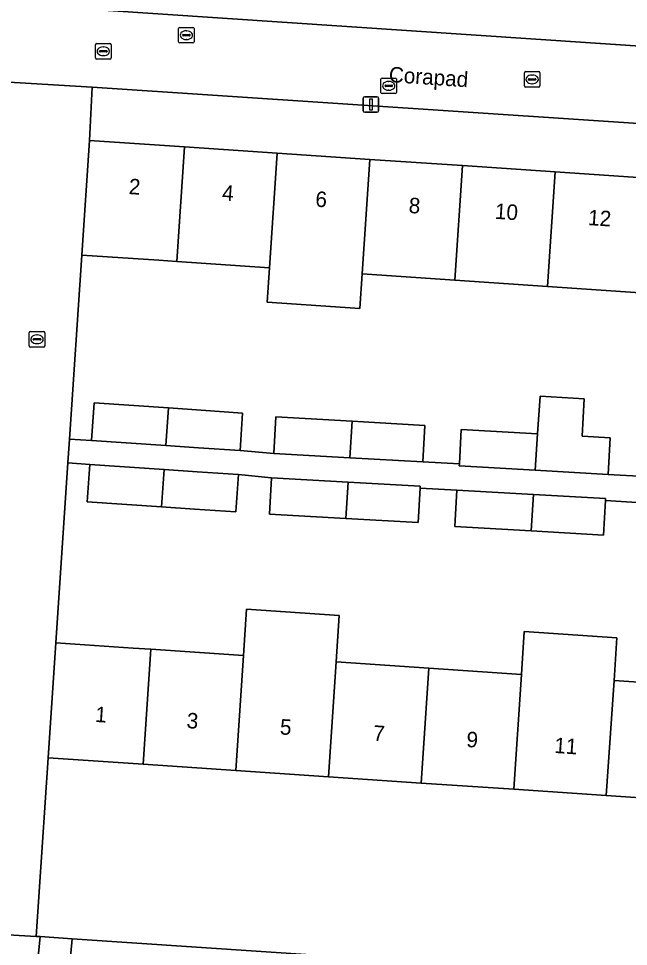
# Model space of a CAD drawing. Extents: x 161848 to 162726, y 385382 to 386521.
# Drawn here: x 162057.8 to 162097.2, y 385869.2 to 385929.1 of the extents above; entities that cross this region are included whole.
import ezdxf

# ---------------------------------------------------------------- set-up
doc = ezdxf.new("R2010")
doc.units = 0
for name, color, linetype in [('IMGEO_Brandkraan', 7, 'Continuous'), ('IMGEO_Erf', 7, 'Continuous'), ('IMGEO_Kolk', 7, 'Continuous'), ('IMGEO_Lichtmast', 7, 'Continuous'), ('IMGEO_Muur', 7, 'Continuous'), ('IMGEO_Openbare_ruimte_label', 7, 'Continuous'), ('IMGEO_Pand', 7, 'Continuous'), ('IMGEO_Pand_nummerreeks', 7, 'Continuous'), ('IMGEO_Rijbaan_lokaal_open', 7, 'Continuous'), ('IMGEO_Rioolput', 7, 'Continuous'), ('IMGEO_Voetpad_open', 7, 'Continuous'), ('IMGEO_Woonerf_open', 7, 'Continuous')]:
    doc.layers.add(name, color=color, linetype=linetype)

msp = doc.modelspace()

# ---------------------------------------------------------------- linework, layer by layer
at = {"layer": 'IMGEO_Brandkraan'}
for p, q in [((162081.246, 385924.369), (162081.246, 385925.221)), ((162081.321, 385925.295), (162082.173, 385925.295)), ((162081.734, 385925.075), (162081.759, 385925.075)), ((162082.247, 385925.221), (162082.247, 385924.369)), ((162082.173, 385924.295), (162081.321, 385924.295)), ((162081.505, 385924.789), (162081.505, 385924.801)), ((162081.943, 385924.752), (162081.545, 385924.752)), ((162081.548, 385924.838), (162081.946, 385924.838)), ((162081.757, 385924.515), (162081.732, 385924.515)), ((162081.989, 385924.801), (162081.989, 385924.789))]:
    msp.add_line(p, q, dxfattribs=at)
for points in [[(162081.246, 385924.369), (162081.246, 385925.221)], [(162081.321, 385925.295), (162082.173, 385925.295)], [(162082.247, 385925.221), (162082.247, 385924.369)], [(162082.173, 385924.295), (162081.321, 385924.295)]]:
    msp.add_lwpolyline(points, dxfattribs=at)
for centre, radius, start, end in [((162081.323, 385925.219), 0.0765, 91.55205, 178.44795), ((162081.323, 385925.219), 0.0765, 91.55205, 178.44795), ((162082.171, 385925.219), 0.0765, 1.55205, 88.44795), ((162082.171, 385925.219), 0.0765, 1.55205, 88.44795), ((162081.323, 385924.371), 0.0765, 181.55205, 268.44795), ((162081.323, 385924.371), 0.0765, 181.55205, 268.44795), ((162081.545, 385924.798), 0.0403, 85.87752, 175.75265), ((162081.542, 385924.788), 0.0366, 178.93798, 274.71019), ((162081.946, 385924.795), 0.043, 264.86636, 352.45326), ((162081.95, 385924.8), 0.0386, 1.73085, 96.63898), ((162082.171, 385924.371), 0.0765, 271.55205, 358.44795), ((162082.171, 385924.371), 0.0765, 271.55205, 358.44795)]:
    msp.add_arc(centre, radius, start, end, dxfattribs=at)
for centre, major_axis, ratio, start_param, end_param in [((162081.733, 385924.795), (-0.387, 0.002), 0.722429, 4.712389, 7.853982), ((162081.758, 385924.795), (-0.39, 0.002), 0.717154, 1.570796, 4.712389)]:
    msp.add_ellipse(centre, major_axis=major_axis, ratio=ratio, start_param=start_param, end_param=end_param, dxfattribs=at)
at = {"layer": 'IMGEO_Erf'}
for points in [[(162111.951, 385937.967), (162105.776, 385938.384), (162099.785, 385938.788), (162093.802, 385939.192), (162087.814, 385939.596), (162081.834, 385939.999), (162075.835, 385940.404), (162069.859, 385940.808), (162063.747, 385941.22), (162062.973, 385929.704), (162111.178, 385926.464)], [(162110.864, 385921.497), (162062.576, 385924.706), (162062.409, 385921.268), (162068.56, 385920.853), (162074.547, 385920.449), (162080.533, 385920.045), (162086.52, 385919.641), (162092.506, 385919.236), (162098.492, 385918.832), (162104.479, 385918.428), (162110.632, 385918.013)], [(162107.935, 385878.155), (162101.794, 385878.569), (162095.807, 385878.973), (162089.821, 385879.377), (162083.835, 385879.781), (162077.848, 385880.186), (162071.862, 385880.59), (162065.875, 385880.994), (162059.734, 385881.408), (162058.972, 385869.883), (162059.222, 385869.866), (162061.295, 385869.726), (162085.397, 385868.102), (162087.531, 385867.959), (162107.159, 385866.636)]]:
    msp.add_lwpolyline(points, close=True, dxfattribs=at)
for points in [[(162097.992, 385911.436), (162092.006, 385911.84), (162086.02, 385912.244), (162080.033, 385912.648), (162079.884, 385910.429), (162073.897, 385910.834), (162074.047, 385913.052), (162068.06, 385913.456), (162066.899, 385913.534), (162061.91, 385913.871), (162061.115, 385901.991), (162062.543, 385901.895), (162062.706, 385904.319), (162067.507, 385903.995), (162069.631, 385903.852), (162072.304, 385903.662), (162072.138, 385901.245), (162074.33, 385901.063), (162074.463, 385903.417), (162079.39, 385903.138), (162084.08, 385902.873), (162083.947, 385900.519), (162086.31, 385900.385), (162086.436, 385902.608), (162091.363, 385902.329), (162091.527, 385904.756), (162094.38, 385904.595), (162094.243, 385902.166), (162096.053, 385902.064), (162095.92, 385899.71), (162098.283, 385899.576)], [(162098.118, 385897.88), (162095.755, 385898.014), (162095.629, 385895.79), (162090.947, 385896.055), (162086.012, 385896.334), (162086.145, 385898.688), (162083.782, 385898.822), (162083.656, 385896.599), (162078.974, 385896.864), (162074.039, 385897.143), (162074.172, 385899.497), (162072.034, 385899.699), (162071.871, 385897.286), (162069.196, 385897.467), (162067.075, 385897.61), (162062.271, 385897.934), (162062.434, 385900.348), (162061.012, 385900.444), (162060.235, 385888.83), (162065.224, 385888.493), (162066.376, 385888.417), (162072.363, 385888.013), (162072.565, 385891.006), (162078.551, 385890.602), (162078.349, 385887.609), (162084.336, 385887.204), (162090.322, 385886.799), (162090.507, 385889.565), (162096.492, 385889.161), (162096.308, 385886.395), (162102.295, 385885.991)]]:
    msp.add_lwpolyline(points, dxfattribs=at)
at = {"layer": 'IMGEO_Kolk'}
for p, q in [((162062.803, 385926.6), (162062.803, 385927.452)), ((162062.878, 385927.526), (162063.73, 385927.526)), ((162063.291, 385927.306), (162063.316, 385927.306)), ((162063.804, 385927.452), (162063.804, 385926.6)), ((162063.062, 385927.02), (162063.062, 385927.032)), ((162063.5, 385926.983), (162063.102, 385926.983)), ((162063.105, 385927.069), (162063.503, 385927.069)), ((162063.314, 385926.746), (162063.289, 385926.746)), ((162063.546, 385927.032), (162063.546, 385927.02)), ((162063.73, 385926.526), (162062.878, 385926.526)), ((162090.514, 385924.785), (162090.514, 385925.637)), ((162090.589, 385925.711), (162091.441, 385925.711)), ((162091.002, 385925.491), (162091.027, 385925.491)), ((162091.515, 385925.637), (162091.515, 385924.785)), ((162090.773, 385925.205), (162090.773, 385925.217)), ((162091.211, 385925.168), (162090.813, 385925.168)), ((162090.816, 385925.254), (162091.214, 385925.254)), ((162091.025, 385924.931), (162091, 385924.931)), ((162091.257, 385925.217), (162091.257, 385925.205)), ((162091.441, 385924.711), (162090.589, 385924.711)), ((162058.519, 385908.006), (162058.519, 385908.858)), ((162058.594, 385908.932), (162059.446, 385908.932)), ((162059.007, 385908.712), (162059.032, 385908.712)), ((162059.52, 385908.858), (162059.52, 385908.006)), ((162058.778, 385908.426), (162058.778, 385908.438)), ((162059.216, 385908.389), (162058.818, 385908.389)), ((162058.821, 385908.475), (162059.219, 385908.475)), ((162059.03, 385908.152), (162059.005, 385908.152)), ((162059.262, 385908.438), (162059.262, 385908.426)), ((162059.446, 385907.932), (162058.594, 385907.932))]:
    msp.add_line(p, q, dxfattribs=at)
for points in [[(162062.803, 385926.6), (162062.803, 385927.452)], [(162062.878, 385927.526), (162063.73, 385927.526)], [(162063.804, 385927.452), (162063.804, 385926.6)], [(162063.73, 385926.526), (162062.878, 385926.526)], [(162090.514, 385924.785), (162090.514, 385925.637)], [(162090.589, 385925.711), (162091.441, 385925.711)], [(162091.515, 385925.637), (162091.515, 385924.785)], [(162091.441, 385924.711), (162090.589, 385924.711)], [(162058.519, 385908.006), (162058.519, 385908.858)], [(162058.594, 385908.932), (162059.446, 385908.932)], [(162059.52, 385908.858), (162059.52, 385908.006)], [(162059.446, 385907.932), (162058.594, 385907.932)]]:
    msp.add_lwpolyline(points, dxfattribs=at)
for centre, radius, start, end in [((162062.88, 385927.45), 0.0765, 91.55205, 178.44795), ((162062.88, 385927.45), 0.0765, 91.55205, 178.44795), ((162063.728, 385927.45), 0.0765, 1.55205, 88.44795), ((162063.728, 385927.45), 0.0765, 1.55205, 88.44795), ((162063.102, 385927.029), 0.0403, 85.87752, 175.75265), ((162063.099, 385927.019), 0.0366, 178.93798, 274.71019), ((162063.503, 385927.026), 0.043, 264.86636, 352.45326), ((162063.507, 385927.031), 0.0386, 1.73085, 96.63898), ((162062.88, 385926.602), 0.0765, 181.55205, 268.44795), ((162062.88, 385926.602), 0.0765, 181.55205, 268.44795), ((162063.728, 385926.602), 0.0765, 271.55205, 358.44795), ((162063.728, 385926.602), 0.0765, 271.55205, 358.44795), ((162090.591, 385925.635), 0.0765, 91.55205, 178.44795), ((162090.591, 385925.635), 0.0765, 91.55205, 178.44795), ((162091.439, 385925.635), 0.0765, 1.55205, 88.44795), ((162091.439, 385925.635), 0.0765, 1.55205, 88.44795), ((162090.813, 385925.214), 0.0403, 85.87752, 175.75265), ((162090.81, 385925.204), 0.0366, 178.93798, 274.71019), ((162091.214, 385925.211), 0.043, 264.86636, 352.45326), ((162091.218, 385925.216), 0.0386, 1.73085, 96.63898), ((162090.591, 385924.787), 0.0765, 181.55205, 268.44795), ((162090.591, 385924.787), 0.0765, 181.55205, 268.44795), ((162091.439, 385924.787), 0.0765, 271.55205, 358.44795), ((162091.439, 385924.787), 0.0765, 271.55205, 358.44795), ((162058.596, 385908.856), 0.0765, 91.55205, 178.44795), ((162058.596, 385908.856), 0.0765, 91.55205, 178.44795), ((162059.444, 385908.856), 0.0765, 1.55205, 88.44795), ((162059.444, 385908.856), 0.0765, 1.55205, 88.44795), ((162058.818, 385908.435), 0.0403, 85.87752, 175.75265), ((162058.815, 385908.425), 0.0366, 178.93798, 274.71019), ((162059.219, 385908.432), 0.043, 264.86636, 352.45326), ((162059.223, 385908.437), 0.0386, 1.73085, 96.63898), ((162058.596, 385908.008), 0.0765, 181.55205, 268.44795), ((162058.596, 385908.008), 0.0765, 181.55205, 268.44795), ((162059.444, 385908.008), 0.0765, 271.55205, 358.44795), ((162059.444, 385908.008), 0.0765, 271.55205, 358.44795)]:
    msp.add_arc(centre, radius, start, end, dxfattribs=at)
for centre, major_axis, ratio, start_param, end_param in [((162063.29, 385927.026), (-0.387, 0.002), 0.722429, 4.712389, 7.853982), ((162063.315, 385927.026), (-0.39, 0.002), 0.717154, 1.570796, 4.712389), ((162091.001, 385925.211), (-0.387, 0.002), 0.722429, 4.712389, 7.853982), ((162091.026, 385925.211), (-0.39, 0.002), 0.717154, 1.570796, 4.712389), ((162059.006, 385908.432), (-0.387, 0.002), 0.722429, 4.712389, 7.853982), ((162059.031, 385908.432), (-0.39, 0.002), 0.717154, 1.570796, 4.712389)]:
    msp.add_ellipse(centre, major_axis=major_axis, ratio=ratio, start_param=start_param, end_param=end_param, dxfattribs=at)
at = {"layer": 'IMGEO_Lichtmast'}
for p, q in [((162080.098, 385923.189), (162080.098, 385923.989)), ((162080.098, 385923.989), (162080.098, 385923.189)), ((162080.198, 385924.089), (162080.988, 385924.089)), ((162080.988, 385924.089), (162080.198, 385924.089)), ((162081.088, 385923.989), (162081.088, 385923.189)), ((162081.088, 385923.189), (162081.088, 385923.989)), ((162080.988, 385923.089), (162080.198, 385923.089)), ((162080.198, 385923.089), (162080.988, 385923.089))]:
    msp.add_line(p, q, dxfattribs=at)
msp.add_lwpolyline([(162080.518, 385923.964), (162080.668, 385923.964), (162080.668, 385923.214), (162080.518, 385923.214), (162080.518, 385923.964)], dxfattribs=at)
for centre, start, end in [((162080.198, 385923.989), 90, 180), ((162080.198, 385923.989), 90, 180), ((162080.988, 385923.989), 0, 90), ((162080.988, 385923.989), 360, 90), ((162080.198, 385923.189), 180, 270), ((162080.198, 385923.189), 180, 270), ((162080.988, 385923.189), 270, 0), ((162080.988, 385923.189), 270, 0)]:
    msp.add_arc(centre, 0.1, start, end, dxfattribs=at)
at = {"layer": 'IMGEO_Muur'}
for points in [[(162061.115, 385901.991), (162061.91, 385913.871)], [(162061.012, 385900.444), (162060.235, 385888.83)]]:
    msp.add_lwpolyline(points, dxfattribs=at)
at = {"layer": 'IMGEO_Pand'}
for points in [[(162061.91, 385913.871), (162066.899, 385913.534), (162068.06, 385913.456), (162068.56, 385920.853), (162062.409, 385921.268)], [(162074.547, 385920.449), (162068.56, 385920.853), (162068.06, 385913.456), (162074.047, 385913.052)], [(162073.897, 385910.834), (162079.884, 385910.429), (162080.033, 385912.648), (162080.533, 385920.045), (162074.547, 385920.449), (162074.047, 385913.052)], [(162080.033, 385912.648), (162086.02, 385912.244), (162086.52, 385919.641), (162080.533, 385920.045)], [(162092.506, 385919.236), (162086.52, 385919.641), (162086.02, 385912.244), (162092.006, 385911.84)], [(162098.492, 385918.832), (162092.506, 385919.236), (162092.006, 385911.84), (162097.992, 385911.436)], [(162096.053, 385902.064), (162094.243, 385902.166), (162094.38, 385904.595), (162091.527, 385904.756), (162091.363, 385902.329), (162091.204, 385899.976), (162095.92, 385899.71)], [(162062.706, 385904.319), (162062.543, 385901.895), (162067.343, 385901.571), (162067.507, 385903.995)], [(162069.465, 385901.428), (162072.138, 385901.245), (162072.304, 385903.662), (162069.631, 385903.852), (162067.507, 385903.995), (162067.343, 385901.571)], [(162074.463, 385903.417), (162074.33, 385901.063), (162079.231, 385900.785), (162079.39, 385903.138)], [(162083.947, 385900.519), (162084.08, 385902.873), (162079.39, 385903.138), (162079.231, 385900.785)], [(162091.363, 385902.329), (162086.436, 385902.608), (162086.31, 385900.385), (162086.303, 385900.254), (162091.204, 385899.976)], [(162062.434, 385900.348), (162062.271, 385897.934), (162067.075, 385897.61), (162067.238, 385900.023)], [(162069.196, 385897.467), (162071.871, 385897.286), (162072.034, 385899.699), (162069.36, 385899.88), (162067.238, 385900.023), (162067.075, 385897.61)], [(162074.172, 385899.497), (162074.039, 385897.143), (162078.974, 385896.864), (162079.132, 385899.216)], [(162083.782, 385898.822), (162083.789, 385898.953), (162079.132, 385899.216), (162078.974, 385896.864), (162083.656, 385896.599)], [(162086.145, 385898.688), (162086.012, 385896.334), (162090.947, 385896.055), (162091.106, 385898.407)], [(162095.755, 385898.014), (162095.762, 385898.144), (162091.106, 385898.407), (162090.947, 385896.055), (162095.629, 385895.79)], [(162078.551, 385890.602), (162072.565, 385891.006), (162072.363, 385888.013), (162071.862, 385880.59), (162077.848, 385880.186), (162078.349, 385887.609)], [(162089.821, 385879.377), (162095.807, 385878.973), (162096.308, 385886.395), (162096.492, 385889.161), (162090.507, 385889.565), (162090.322, 385886.799)], [(162059.734, 385881.408), (162065.875, 385880.994), (162066.376, 385888.417), (162065.224, 385888.493), (162060.235, 385888.83)], [(162065.875, 385880.994), (162071.862, 385880.59), (162072.363, 385888.013), (162066.376, 385888.417)], [(162077.848, 385880.186), (162083.835, 385879.781), (162084.336, 385887.204), (162078.349, 385887.609)], [(162090.322, 385886.799), (162084.336, 385887.204), (162083.835, 385879.781), (162089.821, 385879.377)], [(162102.295, 385885.991), (162096.308, 385886.395), (162095.807, 385878.973), (162101.794, 385878.569)]]:
    msp.add_lwpolyline(points, close=True, dxfattribs=at)
at = {"layer": 'IMGEO_Rijbaan_lokaal_open'}
msp.add_lwpolyline([(162050.963, 385870.339), (162058.972, 385869.883), (162059.734, 385881.408), (162060.235, 385888.83), (162061.012, 385900.444), (162061.115, 385901.991), (162061.91, 385913.871), (162062.409, 385921.268), (162062.576, 385924.706), (162054.686, 385925.183)], dxfattribs=at)
at = {"layer": 'IMGEO_Rioolput'}
for p, q in [((162068.171, 385927.639), (162068.171, 385928.491)), ((162068.246, 385928.565), (162069.098, 385928.565)), ((162069.172, 385928.491), (162069.172, 385927.639)), ((162068.43, 385928.059), (162068.43, 385928.071)), ((162068.868, 385928.022), (162068.47, 385928.022)), ((162068.473, 385928.108), (162068.871, 385928.108)), ((162068.659, 385928.345), (162068.684, 385928.345)), ((162068.914, 385928.071), (162068.914, 385928.059)), ((162069.098, 385927.565), (162068.246, 385927.565)), ((162068.682, 385927.785), (162068.657, 385927.785))]:
    msp.add_line(p, q, dxfattribs=at)
for points in [[(162068.171, 385927.639), (162068.171, 385928.491)], [(162068.246, 385928.565), (162069.098, 385928.565)], [(162069.172, 385928.491), (162069.172, 385927.639)], [(162069.098, 385927.565), (162068.246, 385927.565)]]:
    msp.add_lwpolyline(points, dxfattribs=at)
for centre, radius, start, end in [((162068.248, 385928.489), 0.0765, 91.55205, 178.44795), ((162068.248, 385928.489), 0.0765, 91.55205, 178.44795), ((162069.096, 385928.489), 0.0765, 1.55205, 88.44795), ((162069.096, 385928.489), 0.0765, 1.55205, 88.44795), ((162068.47, 385928.068), 0.0403, 85.87752, 175.75265), ((162068.467, 385928.058), 0.0366, 178.93798, 274.71019), ((162068.871, 385928.065), 0.043, 264.86636, 352.45326), ((162068.875, 385928.07), 0.0386, 1.73085, 96.63898), ((162068.248, 385927.641), 0.0765, 181.55205, 268.44795), ((162068.248, 385927.641), 0.0765, 181.55205, 268.44795), ((162069.096, 385927.641), 0.0765, 271.55205, 358.44795), ((162069.096, 385927.641), 0.0765, 271.55205, 358.44795)]:
    msp.add_arc(centre, radius, start, end, dxfattribs=at)
for centre, major_axis, ratio, start_param, end_param in [((162068.658, 385928.065), (-0.387, 0.002), 0.722429, 4.712389, 7.853982), ((162068.683, 385928.065), (-0.39, 0.002), 0.717154, 1.570796, 4.712389)]:
    msp.add_ellipse(centre, major_axis=major_axis, ratio=ratio, start_param=start_param, end_param=end_param, dxfattribs=at)
at = {"layer": 'IMGEO_Voetpad_open'}
msp.add_lwpolyline([(162098.283, 385899.576), (162095.92, 385899.71), (162091.204, 385899.976), (162086.303, 385900.254), (162086.31, 385900.385), (162083.947, 385900.519), (162079.231, 385900.785), (162074.33, 385901.063), (162072.138, 385901.245), (162069.465, 385901.428), (162067.343, 385901.571), (162062.543, 385901.895), (162061.115, 385901.991), (162061.012, 385900.444), (162062.434, 385900.348), (162067.238, 385900.023), (162069.36, 385899.88), (162072.034, 385899.699), (162074.172, 385899.497), (162079.132, 385899.216), (162083.789, 385898.953), (162083.782, 385898.822), (162086.145, 385898.688), (162091.106, 385898.407), (162095.762, 385898.144), (162095.755, 385898.014), (162098.118, 385897.88)], dxfattribs=at)
at = {"layer": 'IMGEO_Woonerf_open'}
msp.add_lwpolyline([(162112.645, 385926.365), (162111.178, 385926.464), (162062.973, 385929.704), (162061.492, 385929.804), (162061.373, 385929.812), (162061.366, 385929.711), (162055.027, 385930.112), (162046.462, 385930.654), (162046.474, 385930.817), (162043.317, 385931.03), (162042.949, 385931.049), (162042.191, 385931.089), (162041.849, 385925.93), (162042.942, 385925.829), (162046.771, 385925.731), (162054.686, 385925.183), (162062.576, 385924.706), (162110.864, 385921.497), (162112.048, 385921.418), (162123.446, 385920.647), (162129.418, 385920.249), (162134.187, 385919.947)], dxfattribs=at)
for points in [[(162059.222, 385869.866), (162058.972, 385869.883), (162050.963, 385870.339), (162043.014, 385870.751), (162038.259, 385870.998), (162037.888, 385866.206), (162038.481, 385866.177), (162042.327, 385865.987), (162050.612, 385865.355), (162057.104, 385864.918), (162058.551, 385864.821), (162058.738, 385864.808)], [(162061.295, 385869.726), (162059.222, 385869.866), (162058.738, 385864.808), (162060.825, 385864.668)], [(162085.397, 385868.102), (162061.295, 385869.726), (162060.825, 385864.668), (162085.081, 385863.036)]]:
    msp.add_lwpolyline(points, close=True, dxfattribs=at)

# ---------------------------------------------------------------- texts
at = {"layer": 'IMGEO_Openbare_ruimte_label'}
msp.add_text('Corapad', height=1, rotation=356.21641, dxfattribs=at).set_placement((162081.732, 385925.039))
at = {"layer": 'IMGEO_Pand_nummerreeks'}
for s, rotation, p in [('2', 356.13846, (162064.926, 385917.811)), ('4', 356.13846, (162070.956, 385917.404)), ('6', 356.13846, (162076.983, 385916.997)), ('8', 356.13846, (162083.015, 385916.59)), ('10', 356.13846, (162088.583, 385916.214)), ('12', 356.13846, (162094.605, 385915.808)), ('1', 356.13906, (162062.755, 385883.73)), ('3', 356.13906, (162068.667, 385883.331)), ('5', 356.13906, (162074.692, 385882.925)), ('7', 356.13906, (162080.717, 385882.518)), ('9', 356.13906, (162086.742, 385882.112)), ('11', 356.13906, (162092.422, 385881.728))]:
    msp.add_text(s, height=1, rotation=rotation, dxfattribs=at).set_placement(p)

doc.saveas('drawing.dxf')
